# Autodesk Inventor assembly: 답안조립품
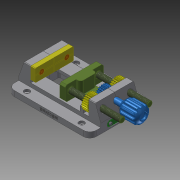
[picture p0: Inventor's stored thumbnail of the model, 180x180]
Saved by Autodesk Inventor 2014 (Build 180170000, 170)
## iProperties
Created: 2018-03
Part Number: 답안조립품
Document SubType Name: Assembly
Designer: kb542
Author: kb542
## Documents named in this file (10)
- C:\Users\kb542\Desktop\380307V1026\답안조립품.iam
- C:\Users\kb542\Desktop\380307V1026\바이스본체 A.ipt
- C:\Users\kb542\Desktop\380307V1026\고정 플레이트.ipt
- C:\Users\kb542\Desktop\380307V1026\바이스본체 B.ipt
- C:\Users\kb542\Desktop\380307V1026\스퍼기어.ipt
- C:\Users\kb542\Desktop\380307V1026\슬라이딩 부품.ipt
- C:\Users\kb542\Desktop\380307V1026\십자오목머리나사 M3.ipt
- C:\Users\kb542\Desktop\380307V1026\십자오목머리나사 M4.ipt
- C:\Users\kb542\Desktop\380307V1026\지지대.ipt
- C:\Users\kb542\Desktop\380307V1026\핸들.ipt
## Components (3 placed, 2 different names)
1. 고정 플레이트:1
2. 핸들:1 — 플러쉬:2, 각도:1
3. 고정 플레이트:2
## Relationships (2: Flush 1, Angle 1)
- 플러쉬:2 [Flush]: 핸들:1
- 각도:1 [Angle]: 핸들:1
